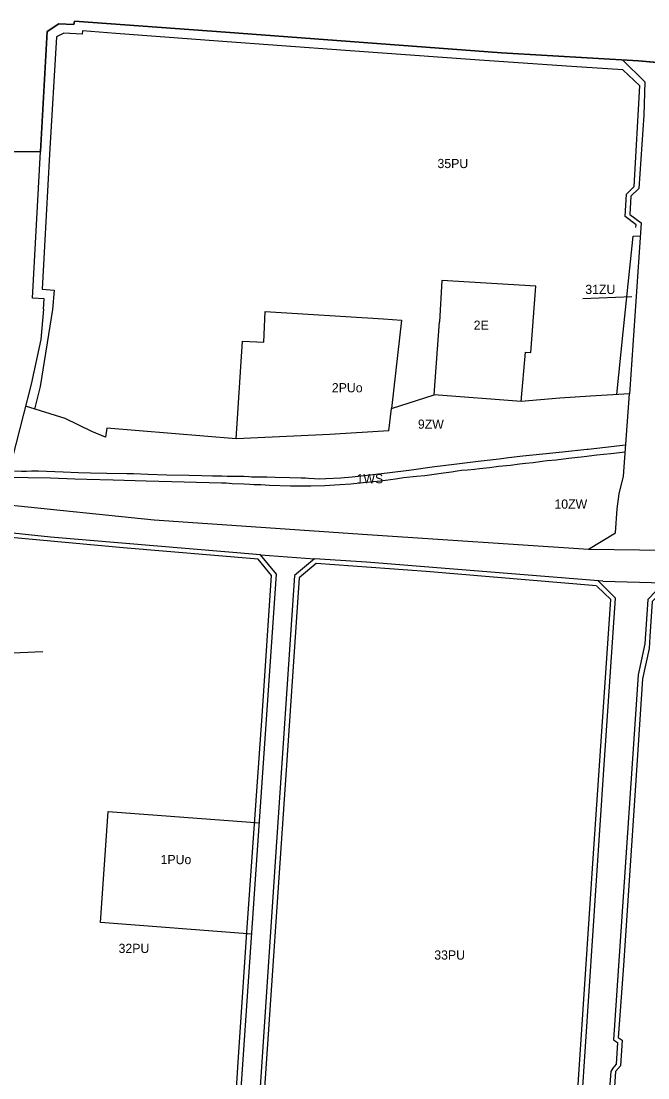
# Model space of a CAD drawing. Extents: x 7428203 to 7432868, y 5542672 to 5545406.
# Drawn here: x 7431420 to 7432101, y 5543958 to 5545107 of the extents above; entities that cross this region are included whole.
import ezdxf

# ---------------------------------------------------------------- set-up
doc = ezdxf.new("R2010")
doc.units = 0
for name, color, linetype in [('__LEGENDA_RAMKA_LOGO_PODZIAŁKA', 7, 'Continuous'), ('_GRANICA_MIASTA', 7, 'Continuous'), ('granicaBulwary', 7, 'Continuous'), ('MPZP_uchwalone_nieobowiazujace jeszcze_SZRAF', 7, 'Continuous')]:
    doc.layers.add(name, color=color, linetype=linetype)

msp = doc.modelspace()

# ---------------------------------------------------------------- linework, layer by layer
at = {"layer": '__LEGENDA_RAMKA_LOGO_PODZIAŁKA'}
msp.add_lwpolyline([(7432213.2, 5545053), (7432091.4, 5545063.6), (7431942.2, 5545072.5), (7431642.1, 5545094.7), (7431477.6, 5545106.8), (7431477.2, 5545103.1), (7431460.7, 5545103.9), (7431448.2, 5545095.6), (7431440.7, 5544965), (7431383.7, 5544964.5)], dxfattribs=at)
at = {"layer": '_GRANICA_MIASTA'}
for p, q in [((7431448.2, 5545095.6), (7431460.7, 5545103.9)), ((7431460.7, 5545103.9), (7431477.2, 5545103.1)), ((7431477.2, 5545103.1), (7431477.6, 5545106.8)), ((7431477.6, 5545106.8), (7431642.1, 5545094.7)), ((7431440.7, 5544965), (7431448.2, 5545095.6)), ((7431642.1, 5545094.7), (7431942.2, 5545072.5)), ((7431942.2, 5545072.5), (7432091.4, 5545063.6)), ((7432074, 5545064.7), (7432098.2, 5545040.8)), ((7432091.4, 5545063.6), (7432213.2, 5545053)), ((7432098.2, 5545040.8), (7432096.9, 5545004.4)), ((7432096.9, 5545004.4), (7432091.5, 5544924.8)), ((7431383.7, 5544964.5), (7431440.7, 5544965)), ((7431432, 5544805.7), (7431440.7, 5544965)), ((7432091.5, 5544924.8), (7432083, 5544916.6)), ((7432083, 5544916.6), (7432082, 5544896.6)), ((7432082, 5544896.6), (7432094, 5544887.5)), ((7432094, 5544887.5), (7432093.7, 5544882.2)), ((7432093.7, 5544882.2), (7432081.8, 5544706.7)), ((7431877.4, 5544824.9), (7431874.7, 5544780)), ((7431979.5, 5544818.7), (7431877.4, 5544824.9)), ((7431974.3, 5544746.4), (7431979.5, 5544818.7)), ((7431444.8, 5544804.9), (7431432, 5544805.7)), ((7431443.9, 5544793.7), (7431444.8, 5544804.9)), ((7431963.7, 5544693.1), (7431968.3, 5544746.8)), ((7431968.3, 5544746.8), (7431974.3, 5544746.4)), ((7432081.8, 5544706.7), (7432081.5, 5544701.7)), ((7431822.5, 5544685.7), (7431868.9, 5544700.5)), ((7432005.8, 5544696.9), (7431963.7, 5544693.1)), ((7432038.9, 5544699), (7432005.8, 5544696.9)), ((7432081.5, 5544701.7), (7432038.9, 5544699)), ((7431819.7, 5544661.3), (7431822.5, 5544685.7)), ((7431653.6, 5544652.8), (7431512.8, 5544664.4)), ((7431755.4, 5544657.4), (7431653.6, 5544652.8)), ((7431819.7, 5544661.3), (7431755.4, 5544657.4)), ((7432036.8, 5544532.5), (7432120.2, 5544531.7)), ((7431680.1, 5544526.5), (7431738.9, 5544522.1)), ((7431738.9, 5544522.1), (7431717.2, 5544503.9)), ((7431795.4, 5544518.7), (7431738.9, 5544522.1)), ((7432052.5, 5544497.8), (7431795.4, 5544518.7)), ((7431717.2, 5544503.9), (7431696.5, 5544198)), ((7432066.3, 5544479.3), (7432047.5, 5544498.2)), ((7432052.5, 5544497.8), (7432118.7, 5544495.9)), ((7432118.7, 5544495.9), (7432101.3, 5544477.8)), ((7432053.7, 5544292.6), (7432066.3, 5544479.3)), ((7432101.3, 5544477.8), (7432098.2, 5544429.8)), ((7432098.2, 5544429.8), (7432090.8, 5544396.2)), ((7432090.8, 5544396.2), (7432064.1, 5543999)), ((7432024.2, 5543851.7), (7432053.7, 5544292.6)), ((7431696.5, 5544198), (7431674.7, 5543875.4)), ((7432064.1, 5543999), (7432068.4, 5543996.1)), ((7432068.4, 5543996.1), (7432066.8, 5543972.7)), ((7432063.5, 5543968.3), (7432061, 5543964.9)), ((7432066.8, 5543972.7), (7432063.5, 5543968.3)), ((7432061, 5543964.9), (7432053, 5543849.8))]:
    msp.add_line(p, q, dxfattribs=at)
for points in [[(7432067.8, 5544700.9), (7432074.7, 5544768.6), (7432082.5, 5544845.2), (7432085.4, 5544873.1), (7432093.1, 5544873.3)], [(7431443.9, 5544793.7), (7431441.1, 5544760.7), (7431430.7, 5544711.9), (7431401.1, 5544597.3), (7431397.1, 5544588.2), (7431402.5, 5544581.1), (7431564.3, 5544564.4), (7431796.5, 5544548.5), (7432036.8, 5544532.5), (7432066.3, 5544550.3), (7432068.2, 5544576.4), (7432070.4, 5544592.9), (7432074.8, 5544612.1), (7432081.5, 5544701.7)], [(7431653.6, 5544652.8), (7431660.6, 5544758.9), (7431683.7, 5544757.6), (7431685, 5544790.9), (7431813.8, 5544783), (7431833.4, 5544781.7), (7431822.5, 5544685.7)], [(7431963.7, 5544693.1), (7431868.9, 5544700.5), (7431874.7, 5544780)], [(7431512.8, 5544664.4), (7431511.4, 5544654.5), (7431496.7, 5544660.5), (7431467.5, 5544674.8), (7431424.6, 5544688.2)], [(7432077.3, 5544645.7), (7432055.5, 5544643.1), (7432036.7, 5544640.9), (7432035.2, 5544640.9), (7432008.5, 5544638.2), (7431990.8, 5544636.4), (7431965.6, 5544633.6), (7431950, 5544631.9), (7431939.7, 5544630.6), (7431916.9, 5544627.9), (7431893.5, 5544625), (7431866.9, 5544621.7), (7431844.5, 5544618.7), (7431817.7, 5544615.4), (7431796.1, 5544612.8), (7431779.9, 5544611), (7431767.6, 5544610), (7431751.1, 5544609), (7431744.3, 5544608.8), (7431738.9, 5544609), (7431732.4, 5544609.5), (7431729.1, 5544609.7), (7431724.5, 5544609.9), (7431712, 5544610.2), (7431696.2, 5544610.7), (7431687.1, 5544610.9), (7431670.8, 5544611.1), (7431667.4, 5544611.2), (7431661.8, 5544611.5), (7431659.4, 5544611.6), (7431651.2, 5544611.5), (7431647.1, 5544611.5), (7431643.7, 5544611.6), (7431638.4, 5544611.9), (7431627.8, 5544612.1), (7431616.1, 5544612.3), (7431602, 5544612.7), (7431578.2, 5544613.2), (7431557.7, 5544613.8), (7431542.1, 5544614.4), (7431534.6, 5544614.4), (7431512.8, 5544615), (7431495.2, 5544615.4), (7431481.6, 5544615.7), (7431465.3, 5544616.3), (7431447.2, 5544617), (7431438.6, 5544617.3), (7431431, 5544617.4), (7431425.7, 5544617.2), (7431420, 5544617.2), (7431412.4, 5544617.3)], [(7431406.7, 5544611.1), (7431427.5, 5544610.7), (7431451.7, 5544610.1), (7431478.3, 5544609.1), (7431491.2, 5544608.9), (7431519.9, 5544607.9), (7431555.8, 5544607), (7431597, 5544606), (7431637.8, 5544604.9), (7431642.7, 5544604.7), (7431649.2, 5544604), (7431661.8, 5544603.7), (7431668.4, 5544603.5), (7431672.9, 5544602.9), (7431680.6, 5544603.1), (7431689.8, 5544602.4), (7431712.8, 5544601.5), (7431734.7, 5544601.5), (7431749.9, 5544601.8), (7431766.3, 5544602.8), (7431778.4, 5544603.8), (7431791.8, 5544605.3), (7431810.5, 5544607), (7431826.9, 5544609.2), (7431835.8, 5544610.5), (7431849.7, 5544612), (7431858.7, 5544612.9), (7431871.6, 5544614.7), (7431879, 5544615.7), (7431887.8, 5544616.6), (7431894.1, 5544617.7), (7431898.8, 5544618.6), (7431905.4, 5544619), (7431912.7, 5544619.5), (7431918.4, 5544620.2), (7431929.1, 5544621.5), (7431939, 5544622.9), (7431952.2, 5544624.1), (7431961.8, 5544625.5), (7431968.4, 5544626.2), (7431976.8, 5544627), (7431986.3, 5544628.4), (7431991.8, 5544629), (7432001.8, 5544629.9), (7432015.1, 5544631.5), (7432032.1, 5544633.5), (7432045.9, 5544635.1), (7432061.3, 5544636.8), (7432076.8, 5544638.6)], [(7431654.5, 5543877.1), (7431672.9, 5544147.4), (7431697.4, 5544505.4), (7431680.1, 5544526.5), (7431451.7, 5544545.8), (7431389.7, 5544552.2)], [(7431670.6, 5544114.2), (7431505.9, 5544126.8), (7431514.5, 5544247.4), (7431678.9, 5544235.1)]]:
    msp.add_lwpolyline(points, dxfattribs=at)
at = {"layer": 'granicaBulwary'}
for p, q in [((7432084.1, 5544807), (7432030.6, 5544804.8)), ((7431443.2, 5544421.1), (7431376.2, 5544418.3))]:
    msp.add_line(p, q, dxfattribs=at)
at = {"layer": 'MPZP_uchwalone_nieobowiazujace jeszcze_SZRAF'}
for p, q in [((7432071.8, 5543971), (7432066.4, 5543964.9)), ((7432066.4, 5543964.9), (7432041.6, 5543621))]:
    msp.add_line(p, q, dxfattribs=at)
for points in [[(7431634, 5545085.1), (7431522.6, 5545093.5), (7431486.5, 5545096.1), (7431486.2, 5545092.5), (7431466.3, 5545093.6), (7431458.3, 5545089.6), (7431450.7, 5544962.2), (7431445.1, 5544862)], [(7432074.4, 5545053.7), (7432013, 5545057.8), (7431913.1, 5545064.6), (7431772.4, 5545075), (7431634, 5545085.1)], [(7432088.4, 5544882.4), (7432088.9, 5544885.2), (7432076.9, 5544894.2), (7432078.1, 5544918.8), (7432086.7, 5544927), (7432092.9, 5545036.4), (7432074.4, 5545053.7)], [(7431445.1, 5544862), (7431442.5, 5544815.5), (7431455.7, 5544814.3), (7431453.8, 5544793.2)], [(7431453.8, 5544793.2), (7431440.5, 5544709.6), (7431434.1, 5544684.9)], [(7431649.5, 5543877.4), (7431655.9, 5543974.9), (7431665.2, 5544116.2), (7431681.8, 5544351.3), (7431692.1, 5544503.9), (7431677.6, 5544521.7), (7431530.6, 5544534.2), (7431408.5, 5544545.2)], [(7432045.5, 5544492.7), (7431860.4, 5544508.5), (7431740.6, 5544517), (7431722.1, 5544501.5), (7431708.6, 5544303.2), (7431682.3, 5543914.6), (7431678.2, 5543855.2), (7431673.2, 5543780.3), (7431671.5, 5543755.5), (7431672.1, 5543735.7), (7431673.7, 5543716.3), (7431676.2, 5543696.5), (7431679, 5543674.2), (7431683.3, 5543670.2), (7431727.1, 5543673.3), (7431761.2, 5543672.6), (7431783.9, 5543669.9), (7431896.2, 5543650.2), (7431993.3, 5543628.2)], [(7431992.9, 5543628.7), (7431992.9, 5543628.7), (7432003.1, 5543637.4), (7432006, 5543673.8), (7432013.2, 5543765.5), (7432019.2, 5543852.1), (7432042.5, 5544201.7), (7432061.2, 5544477.8), (7432045.9, 5544492.6)], [(7432388.8, 5544473.8), (7432120.7, 5544490.7), (7432106.1, 5544475.7), (7432103.7, 5544437.8), (7432102.9, 5544424.5), (7432095.5, 5544391.5), (7432087.5, 5544270.2), (7432075, 5544080), (7432070.5, 5544021), (7432069, 5544001.7), (7432073.6, 5543998.7), (7432071.8, 5543971)]]:
    msp.add_lwpolyline(points, dxfattribs=at)

# ---------------------------------------------------------------- texts
at = {"layer": 'granicaBulwary'}
for s, p in [('35PU', (7431872.6, 5544947)), ('31ZU', (7432033.4, 5544810.1)), ('2E', (7431912, 5544771.2)), ('2PUo', (7431757.7, 5544703.2)), ('9ZW', (7431851.3, 5544663.6)), ('1WS', (7431784.6, 5544604.3)), ('10ZW', (7431999.8, 5544576.7)), ('1PUo', (7431571.4, 5544190.2)), ('32PU', (7431525.7, 5544093.6)), ('33PU', (7431869.1, 5544086.4))]:
    msp.add_text(s, height=10, dxfattribs=at).set_placement(p)

doc.saveas('drawing.dxf')
